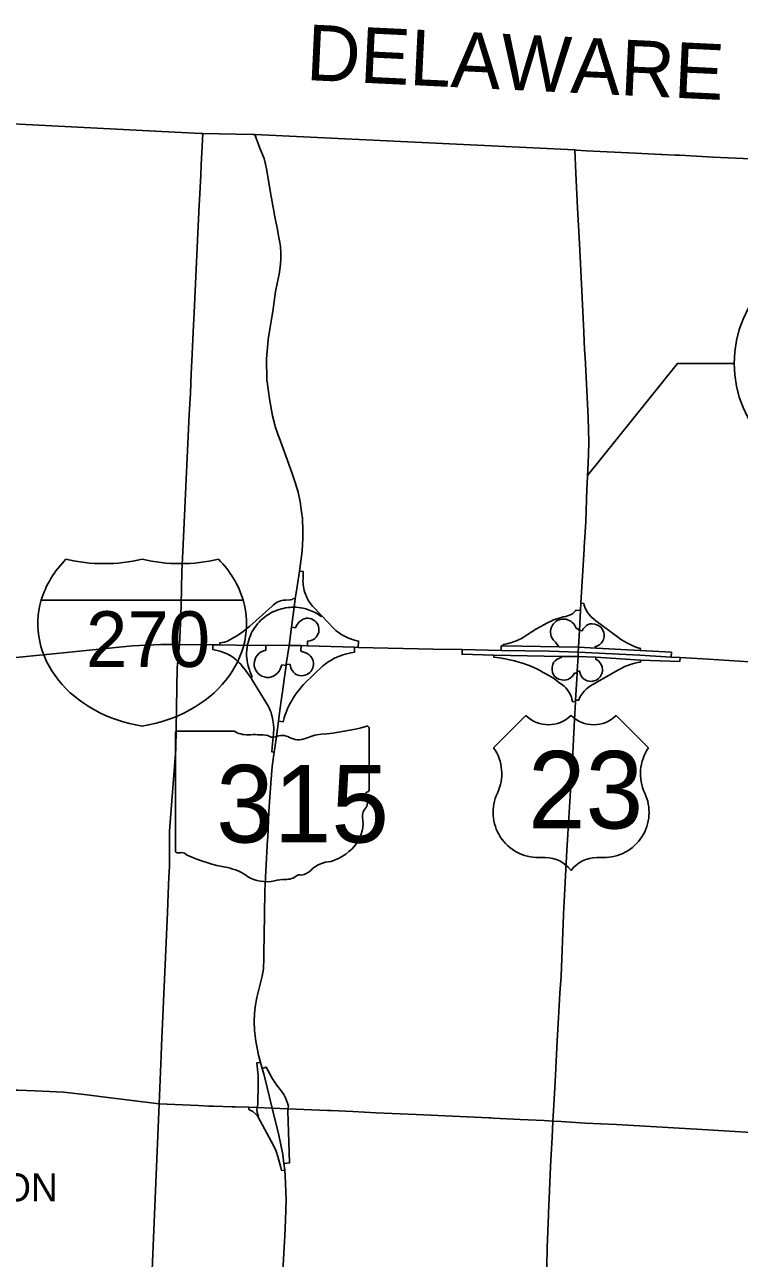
# Model space of a CAD drawing. Extents: x -1146 to -445, y -1283 to -822.
# Drawn here: x -919.9 to -887.8, y -948.5 to -893.1 of the extents above; entities that cross this region are included whole.
import ezdxf

# ---------------------------------------------------------------- set-up
doc = ezdxf.new("R2010")
doc.units = 0
for name, color, linetype in [('Default', 7, 'Continuous'), ('GM_X_Adjacent_County_Text', 7, 'Continuous'), ('GM_X_Corporation_Text', 7, 'Continuous'), ('GM_X_County', 7, 'Continuous'), ('GM_X_Interchange_Ramps', 7, 'Continuous'), ('GM_X_Interstate_Route', 7, 'Continuous'), ('GM_X_Interstate_Shield', 7, 'Continuous'), ('GM_X_State_Route', 7, 'Continuous'), ('GM_X_State_Shield', 7, 'Continuous'), ('GM_X_Township', 7, 'Continuous'), ('GM_X_US_Route', 7, 'Continuous'), ('GM_X_US_Shield', 7, 'Continuous')]:
    doc.layers.add(name, color=color, linetype=linetype)

msp = doc.modelspace()

# ---------------------------------------------------------------- linework, layer by layer
at = {"layer": 'Default'}
msp.add_lwpolyline([(-888.062, -908.344), (-890.609, -908.344), (-894.644, -913.38)], dxfattribs=at)
msp.add_circle((-882.968, -908.344), 5.094, dxfattribs=at)
at = {"layer": 'GM_X_County'}
msp.add_lwpolyline([(-945.796, -896.215), (-936.46, -896.739), (-933.68, -896.859), (-930.577, -897.051), (-929.114, -897.139), (-925.424, -897.327), (-912.021, -898.019), (-911.931, -898.024), (-909.679, -898.071), (-909.589, -898.073), (-895.217, -898.76), (-895.141, -898.773), (-894.703, -898.8), (-892.494, -898.911), (-891.354, -898.969), (-891.291, -898.972), (-890.715, -899.002), (-890.494, -899.002), (-889, -899.078), (-887.326, -899.166)], dxfattribs=at)
at = {"layer": 'GM_X_Interchange_Ramps'}
for points in [[(-904.949, -921.095), (-904.933, -920.816), (-905.121, -920.772), (-905.251, -920.732), (-905.389, -920.68), (-905.507, -920.626), (-905.626, -920.563), (-905.723, -920.504), (-905.808, -920.446), (-905.882, -920.391), (-905.951, -920.335), (-906.014, -920.28), (-906.072, -920.225), (-906.588, -919.681), (-907.001, -919.246), (-907.051, -919.186), (-907.104, -919.113), (-907.14, -919.06), (-907.178, -918.999), (-907.222, -918.921), (-907.258, -918.85), (-907.292, -918.774), (-907.319, -918.705), (-907.345, -918.628), (-907.369, -918.546), (-907.391, -918.456), (-907.408, -918.361), (-907.418, -918.285), (-907.425, -918.203), (-907.428, -918.118), (-907.426, -918.001), (-907.424, -917.698), (-907.424, -917.689), (-907.584, -917.667)], [(-907.777, -918.91), (-907.871, -918.904), (-907.921, -918.944), (-908.002, -918.963), (-908.198, -918.971), (-908.316, -918.98), (-908.439, -919.008), (-908.587, -919.067), (-908.746, -919.187), (-908.811, -919.24), (-909.815, -920.141), (-910.12, -920.384), (-910.377, -920.556), (-910.635, -920.718), (-910.846, -920.831), (-910.959, -920.864), (-911.164, -920.896), (-911.163, -920.988)], [(-906.588, -919.681), (-906.613, -919.705), (-906.668, -919.666), (-906.735, -919.621), (-906.804, -919.579), (-906.885, -919.534), (-906.958, -919.498), (-907.035, -919.463), (-907.107, -919.434), (-907.181, -919.407), (-907.303, -919.369), (-907.414, -919.342), (-907.534, -919.319), (-907.632, -919.306), (-907.732, -919.298), (-907.829, -919.294), (-907.929, -919.295), (-908.017, -919.299), (-908.101, -919.307), (-908.216, -919.324), (-908.32, -919.344), (-908.401, -919.364), (-908.498, -919.392), (-908.593, -919.425), (-908.688, -919.463), (-908.776, -919.503), (-908.869, -919.551), (-908.953, -919.599), (-909.031, -919.648), (-909.101, -919.698), (-909.17, -919.75), (-909.242, -919.81), (-909.316, -919.877), (-909.394, -919.957), (-909.469, -920.041), (-909.534, -920.122), (-909.594, -920.205), (-909.648, -920.287), (-909.705, -920.384), (-909.749, -920.47), (-909.793, -920.565), (-909.833, -920.666), (-909.868, -920.768), (-909.898, -920.874), (-909.918, -920.959), (-909.927, -921.005), (-909.94, -921.082), (-909.956, -921.216), (-909.963, -921.338), (-909.962, -921.477), (-909.956, -921.58), (-909.943, -921.689), (-909.922, -921.811), (-909.895, -921.931), (-909.865, -922.032), (-909.838, -922.111), (-909.818, -922.165), (-909.786, -922.242), (-909.749, -922.321), (-909.708, -922.401), (-909.777, -922.452)], [(-894.966, -919.442), (-895.171, -919.43), (-895.189, -919.454), (-895.253, -919.522), (-895.311, -919.571), (-895.378, -919.616), (-895.455, -919.655), (-895.539, -919.686), (-895.617, -919.705), (-895.733, -919.731), (-895.837, -919.758), (-895.919, -919.781), (-896.032, -919.818), (-896.117, -919.848), (-896.202, -919.881), (-896.282, -919.914), (-896.361, -919.95), (-896.479, -920.007), (-896.905, -920.248), (-896.996, -920.298), (-897.078, -920.347), (-897.155, -920.395), (-897.215, -920.435), (-897.285, -920.484), (-897.351, -920.531), (-897.445, -920.596), (-897.535, -920.65), (-897.614, -920.693), (-897.716, -920.743), (-897.842, -920.799), (-897.936, -920.835), (-898.022, -920.865), (-898.095, -920.888), (-898.165, -920.907), (-898.273, -920.933), (-898.423, -920.963), (-898.424, -921.028)], [(-892.277, -921.239), (-892.271, -921.145), (-892.424, -921.099), (-892.647, -921.017), (-892.885, -920.896), (-893.017, -920.82), (-893.163, -920.727), (-893.303, -920.63), (-894.275, -919.899), (-894.384, -919.812), (-894.5, -919.706), (-894.561, -919.635), (-894.625, -919.547), (-894.676, -919.466), (-894.716, -919.389), (-894.76, -919.29), (-894.79, -919.2), (-894.813, -919.119), (-894.95, -919.11)], [(-907.946, -920.19), (-907.768, -920.215), (-907.722, -920.107), (-907.682, -920.051), (-907.636, -919.999), (-907.582, -919.939), (-907.532, -919.903), (-907.471, -919.859), (-907.425, -919.836), (-907.375, -919.811), (-907.317, -919.801), (-907.269, -919.791), (-907.215, -919.789), (-907.129, -919.797), (-907.045, -919.82), (-906.973, -919.853), (-906.885, -919.916), (-906.833, -919.967), (-906.795, -920.018), (-906.752, -920.098), (-906.727, -920.173), (-906.713, -920.251), (-906.711, -920.324), (-906.722, -920.409), (-906.745, -920.484), (-906.786, -920.566), (-906.839, -920.639), (-906.894, -920.691), (-906.963, -920.74), (-907.036, -920.775), (-907.113, -920.799), (-907.224, -920.812), (-907.233, -921.024)], [(-895.93, -921.069), (-896.091, -920.865), (-896.183, -920.762), (-896.233, -920.688), (-896.272, -920.603), (-896.296, -920.517), (-896.307, -920.434), (-896.305, -920.351), (-896.293, -920.277), (-896.269, -920.196), (-896.225, -920.105), (-896.18, -920.04), (-896.12, -919.977), (-896.05, -919.921), (-895.966, -919.874), (-895.882, -919.844), (-895.772, -919.825), (-895.687, -919.824), (-895.611, -919.834), (-895.543, -919.852), (-895.47, -919.882), (-895.403, -919.921), (-895.337, -919.973), (-895.264, -920.046), (-895.199, -920.139), (-895.151, -920.232), (-895.013, -920.319)], [(-895.013, -920.319), (-894.886, -920.35), (-894.84, -920.268), (-894.778, -920.197), (-894.693, -920.107), (-894.613, -920.066), (-894.53, -920.046), (-894.432, -920.04), (-894.311, -920.051), (-894.222, -920.077), (-894.131, -920.125), (-894.048, -920.193), (-893.997, -920.253), (-893.941, -920.349), (-893.915, -920.424), (-893.899, -920.518), (-893.903, -920.63), (-893.93, -920.736), (-893.977, -920.831), (-894.032, -920.903), (-894.097, -920.964), (-894.167, -921.01), (-894.223, -921.036), (-894.306, -921.06), (-894.263, -921.136)], [(-911.473, -920.982), (-911.478, -921.197), (-911.16, -921.272), (-911.081, -921.294), (-911.006, -921.319), (-910.911, -921.356), (-910.831, -921.392), (-910.756, -921.43), (-910.67, -921.479), (-910.586, -921.532), (-910.518, -921.582), (-910.434, -921.649), (-910.364, -921.711), (-910.291, -921.783), (-910.225, -921.856), (-910.158, -921.939), (-910.1, -922.02), (-910.017, -922.119), (-909.919, -922.257), (-909.777, -922.452), (-909.696, -922.587), (-908.973, -923.757), (-908.93, -923.849), (-908.898, -923.927), (-908.863, -924.025), (-908.836, -924.113), (-908.813, -924.201), (-908.796, -924.279), (-908.779, -924.376), (-908.758, -924.552), (-908.741, -924.731), (-908.749, -924.971), (-908.811, -925.578), (-908.832, -925.784), (-908.721, -925.799)], [(-908.188, -921.908), (-908.374, -921.887), (-908.456, -922.079), (-908.5, -922.161), (-908.576, -922.259), (-908.642, -922.318), (-908.759, -922.39), (-908.844, -922.421), (-908.948, -922.442), (-909.068, -922.443), (-909.178, -922.423), (-909.274, -922.387), (-909.369, -922.331), (-909.463, -922.247), (-909.533, -922.154), (-909.582, -922.054), (-909.614, -921.936), (-909.622, -921.837), (-909.613, -921.73), (-909.583, -921.621), (-909.54, -921.532), (-909.478, -921.443), (-909.406, -921.372), (-909.332, -921.318), (-909.228, -921.267), (-909.099, -921.228), (-909.099, -920.998)], [(-908.531, -924.41), (-908.325, -924.435), (-908.273, -924.257), (-908.239, -924.152), (-908.201, -924.047), (-908.157, -923.937), (-908.104, -923.815), (-908.029, -923.659), (-907.976, -923.557), (-907.904, -923.432), (-907.848, -923.34), (-907.796, -923.26), (-907.734, -923.17), (-907.673, -923.086), (-907.592, -922.982), (-907.499, -922.871), (-907.402, -922.764), (-907.339, -922.697), (-906.537, -921.925), (-906.451, -921.858), (-906.342, -921.78), (-906.236, -921.711), (-906.129, -921.649), (-906.01, -921.586), (-905.914, -921.541), (-905.835, -921.506), (-905.745, -921.471), (-905.645, -921.435), (-905.526, -921.398), (-905.396, -921.364), (-905.279, -921.339), (-905.119, -921.312), (-905.112, -921.086)], [(-907.512, -921.019), (-907.52, -921.26), (-907.341, -921.329), (-907.235, -921.372), (-907.152, -921.426), (-907.086, -921.489), (-907.034, -921.56), (-906.997, -921.63), (-906.971, -921.705), (-906.956, -921.789), (-906.955, -921.868), (-906.964, -921.945), (-906.985, -922.018), (-907.024, -922.102), (-907.068, -922.168), (-907.127, -922.231), (-907.185, -922.276), (-907.25, -922.315), (-907.331, -922.347), (-907.407, -922.363), (-907.487, -922.369), (-907.573, -922.361), (-907.657, -922.34), (-907.73, -922.308), (-907.799, -922.262), (-907.859, -922.202), (-907.904, -922.143), (-907.938, -922.086), (-907.971, -922.01), (-907.993, -921.936), (-908.005, -921.863), (-908.178, -921.843)], [(-890.889, -921.53), (-890.876, -921.312), (-892.277, -921.239), (-894.263, -921.136), (-895.054, -921.086), (-895.93, -921.069), (-898.424, -921.028), (-898.521, -921.027), (-898.523, -921.231)], [(-900.28, -921.197), (-900.279, -921.406), (-898.864, -921.441), (-895.828, -921.499), (-895.073, -921.51), (-894.273, -921.543), (-892.264, -921.664), (-890.503, -921.725), (-890.488, -921.554)], [(-898.864, -921.441), (-898.862, -921.53), (-898.603, -921.563), (-898.353, -921.611), (-898.149, -921.653), (-897.927, -921.706), (-897.728, -921.76), (-897.519, -921.825), (-897.264, -921.915), (-897.064, -921.996), (-896.898, -922.07), (-896.758, -922.143), (-896.632, -922.218), (-896.523, -922.277), (-896.383, -922.357), (-896.276, -922.422), (-896.178, -922.486), (-896.061, -922.574), (-895.928, -922.671), (-895.812, -922.752), (-895.702, -922.845), (-895.618, -922.92), (-895.557, -922.992), (-895.469, -923.124), (-895.415, -923.228), (-895.373, -923.331), (-895.345, -923.421), (-895.322, -923.527), (-895.184, -923.54)], [(-895.117, -922.261), (-895.236, -922.256), (-895.322, -922.393), (-895.419, -922.483), (-895.538, -922.54), (-895.674, -922.569), (-895.807, -922.56), (-895.94, -922.522), (-896.028, -922.473), (-896.11, -922.403), (-896.172, -922.324), (-896.223, -922.218), (-896.242, -922.103), (-896.242, -921.991), (-896.211, -921.867), (-896.168, -921.777), (-896.094, -921.694), (-896.006, -921.626), (-895.907, -921.577), (-895.828, -921.556), (-895.828, -921.499)], [(-895.18, -923.463), (-895.044, -923.47), (-895.002, -923.37), (-894.972, -923.305), (-894.934, -923.242), (-894.887, -923.177), (-894.845, -923.119), (-894.8, -923.063), (-894.744, -923.005), (-894.685, -922.953), (-894.62, -922.903), (-894.556, -922.856), (-894.435, -922.784), (-893.26, -922.105), (-893.137, -922.043), (-893.032, -921.99), (-892.937, -921.946), (-892.84, -921.904), (-892.735, -921.866), (-892.622, -921.832), (-892.519, -921.803), (-892.381, -921.771), (-892.268, -921.756), (-892.264, -921.664)], [(-894.273, -921.543), (-894.273, -921.627), (-894.159, -921.703), (-894.059, -921.819), (-894.019, -921.893), (-893.988, -921.983), (-893.973, -922.071), (-893.975, -922.162), (-893.99, -922.241), (-894.027, -922.335), (-894.084, -922.426), (-894.152, -922.501), (-894.248, -922.562), (-894.356, -922.604), (-894.456, -922.621), (-894.563, -922.616), (-894.668, -922.593), (-894.756, -922.547), (-894.851, -922.478), (-894.918, -922.398), (-894.968, -922.307), (-895.001, -922.169), (-895.113, -922.165)], [(-909.33, -939.732), (-909.497, -939.749), (-909.447, -940.329), (-909.439, -940.71), (-909.463, -941.621), (-909.487, -941.753)], [(-908.102, -941.811), (-908.086, -941.703), (-908.117, -941.562), (-908.219, -941.318), (-908.294, -941.177), (-908.4, -941.028), (-908.62, -940.746), (-908.804, -940.467), (-909.082, -939.941), (-909.255, -940.006)], [(-909.862, -941.742), (-909.862, -941.843), (-909.684, -941.936), (-909.551, -942.054), (-909.477, -942.132), (-909.463, -942.156), (-908.751, -943.458), (-908.632, -943.713), (-908.562, -943.954), (-908.417, -944.447), (-908.392, -944.58), (-908.25, -944.573)], [(-909.487, -941.753), (-909.496, -941.841), (-909.496, -941.843), (-909.481, -941.988), (-909.451, -942.089), (-909.429, -942.132), (-909.463, -942.156)], [(-908.283, -944.273), (-908.04, -944.247), (-908.113, -941.916), (-908.102, -941.811)]]:
    msp.add_lwpolyline(points, dxfattribs=at)
at = {"layer": 'GM_X_Interstate_Route'}
for points in [[(-940.399, -923.41), (-940.223, -923.394), (-939.624, -923.343), (-936.767, -923.076), (-933.009, -922.725), (-929.327, -922.376), (-924.333, -921.901), (-922.171, -921.735), (-918.799, -921.407), (-915.089, -921.031), (-913.815, -920.965), (-913.08, -920.965), (-912.975, -920.974), (-911.473, -920.982), (-911.163, -920.988), (-910.435, -920.998)], [(-910.435, -920.998), (-909.927, -921.005), (-909.099, -920.998), (-908.055, -921.019)], [(-908.055, -921.019), (-908.055, -921.019), (-907.512, -921.019), (-907.233, -921.024), (-905.112, -921.086), (-904.949, -921.095), (-901.586, -921.174), (-900.28, -921.197), (-898.523, -921.231), (-896.354, -921.272), (-895.063, -921.306)], [(-895.063, -921.306), (-892.303, -921.447), (-890.889, -921.53), (-890.488, -921.554)], [(-890.488, -921.554), (-889.219, -921.625), (-885.958, -921.83)]]:
    msp.add_lwpolyline(points, dxfattribs=at)
at = {"layer": 'GM_X_Interstate_Shield'}
msp.add_line((-910.119, -918.969), (-919.184, -918.969), dxfattribs=at)
msp.add_line((-910.119, -918.969), (-919.184, -918.969), dxfattribs=at)
for centre, start_param, end_param in [((-913.479, -920.04), 2.47259, 2.911027), ((-916.363, -912.65), 4.415841, 5.008937), ((-912.939, -912.65), 4.415841, 5.008937), ((-915.823, -920.04), 0.230566, 0.669003), ((-913.479, -920.04), 2.911027, 4.511031), ((-915.823, -920.04), 4.913747, 6.513751)]:
    msp.add_ellipse(centre, major_axis=(5.859, 0), ratio=0.8, start_param=start_param, end_param=end_param, dxfattribs=at)
at = {"layer": 'GM_X_State_Route'}
for points in [[(-908.799, -901.197), (-908.805, -901.167), (-908.857, -900.844), (-909.074, -899.604), (-909.124, -899.346), (-909.176, -899.151), (-909.369, -898.688), (-909.589, -898.073)], [(-908.62, -902.122), (-908.69, -901.766), (-908.753, -901.427), (-908.799, -901.197)], [(-909, -907.293), (-908.998, -907.269), (-908.905, -906.721), (-908.828, -906.268), (-908.785, -906.01), (-908.661, -905.113), (-908.59, -904.752), (-908.501, -904.333), (-908.451, -904.029), (-908.421, -903.693), (-908.421, -903.387), (-908.441, -903.094), (-908.469, -902.916), (-908.514, -902.695), (-908.595, -902.254), (-908.62, -902.122)], [(-908.672, -911.178), (-908.695, -911.11), (-908.796, -910.694), (-908.93, -909.93), (-909.028, -909.273), (-909.052, -909.076), (-909.065, -908.133), (-909, -907.293)], [(-908.503, -911.673), (-908.541, -911.569), (-908.672, -911.178)], [(-908.143, -912.656), (-908.503, -911.673)], [(-907.446, -915.444), (-907.452, -915.31), (-907.491, -915.013), (-907.55, -914.556), (-907.652, -914.123), (-907.775, -913.691), (-907.893, -913.34), (-908.143, -912.656)], [(-907.469, -916.755), (-907.429, -916.191), (-907.432, -915.731), (-907.446, -915.444)], [(-907.691, -918.357), (-907.584, -917.667), (-907.471, -916.781), (-907.469, -916.755)], [(-908.055, -921.019), (-907.946, -920.19), (-907.829, -919.294), (-907.777, -918.91), (-907.691, -918.357)], [(-908.272, -922.534), (-908.188, -921.908), (-908.178, -921.843), (-908.055, -921.019)], [(-908.374, -923.284), (-908.346, -923.089), (-908.272, -922.534)], [(-908.479, -924.035), (-908.374, -923.284)], [(-908.625, -925.105), (-908.576, -924.752), (-908.531, -924.41), (-908.479, -924.035)], [(-908.721, -925.799), (-908.694, -925.6), (-908.625, -925.105)], [(-909.015, -929.718), (-909.01, -929.641), (-908.962, -928.469), (-908.877, -927.2), (-908.808, -926.448), (-908.721, -925.799)], [(-908.81, -941.781), (-909.174, -940.301), (-909.255, -940.006), (-909.33, -939.732), (-909.42, -939.405), (-909.554, -938.773), (-909.611, -938.305), (-909.624, -937.9), (-909.607, -937.549), (-909.584, -937.238), (-909.499, -936.81), (-909.415, -936.453), (-909.264, -935.865), (-909.209, -935.526), (-909.185, -935.048), (-909.18, -934.84), (-909.162, -933.116), (-909.146, -932.029), (-909.1, -931.125), (-909.015, -929.718)], [(-920.317, -940.976), (-920.231, -940.979), (-919.456, -941.009), (-918.184, -941.075), (-917.119, -941.192), (-916.433, -941.283), (-913.888, -941.586), (-912.12, -941.674), (-911.653, -941.693)], [(-911.653, -941.693), (-911.431, -941.702), (-910.604, -941.73), (-910.48, -941.732)], [(-910.48, -941.732), (-909.862, -941.742), (-909.487, -941.753), (-908.81, -941.781)], [(-908.81, -941.781), (-908.102, -941.811), (-906.329, -941.886)], [(-908.283, -944.273), (-908.328, -943.863), (-908.512, -943.006), (-908.81, -941.781)], [(-906.329, -941.886), (-906.162, -941.893), (-905.189, -941.941)], [(-905.189, -941.941), (-904.138, -941.993), (-902.349, -942.064), (-899.078, -942.214), (-898.985, -942.223)], [(-898.985, -942.223), (-898.863, -942.236), (-897.676, -942.296), (-896.587, -942.342), (-896.201, -942.368)], [(-896.201, -942.368), (-895.832, -942.39), (-894.745, -942.457), (-893.343, -942.526), (-891.541, -942.631), (-890.526, -942.687), (-889.734, -942.737), (-888.271, -942.817), (-887.262, -942.874), (-886.455, -942.924), (-885.522, -942.97)], [(-908.22, -946.809), (-908.183, -945.893), (-908.222, -944.825), (-908.25, -944.573), (-908.283, -944.273)], [(-908.513, -952.597), (-908.427, -950.591), (-908.354, -949.36), (-908.249, -947.514), (-908.22, -946.809)]]:
    msp.add_lwpolyline(points, dxfattribs=at)
at = {"layer": 'GM_X_State_Shield'}
for p, q in [((-913.154, -924.947), (-913.154, -930.23)), ((-910.52, -924.856), (-913.069, -924.856)), ((-904.453, -927.488), (-904.453, -924.725)), ((-904.454, -927.488), (-904.453, -927.488))]:
    msp.add_line(p, q, dxfattribs=at)
for centre, major_axis, start_param, end_param in [((-913.054, -924.935), (0.101, 0), 1.712693, 3.28349), ((-909.914, -924.242), (0.978, 0), 4.042523, 4.731795), ((-909.589, -927.822), (3.51, 0), 1.404758, 1.657858), ((-908.793, -924.908), (0.282, 0), 3.836095, 5.185415), ((-908.378, -925.519), (0.586, 0), 0.950623, 2.079405), ((-906.376, -926.469), (1.856, 0), 1.699011, 2.107814), ((-907.553, -917.653), (9.227, 0), 4.814394, 5.042369), ((-904.55, -924.713), (0.0969, 0), 6.141152, 7.989035), ((-907.622, -924.681), (0.705, 0), 4.081561, 5.145723), ((-904.476, -927.691), (0.15, 0), 1.883978, 3.671073), ((-905.429, -928.041), (0.9, 0), 5.934695, 6.695948), ((-904.556, -927.499), (0.104, 0), 5.05454, 6.418171), ((-904.106, -928.645), (0.655, 0), 2.387724, 3.262537), ((-907.036, -928.997), (2.308, 0), 5.101752, 6.440018), ((-913.054, -930.241), (0.102, 0), 3.00124, 4.508301), ((-913.038, -929.701), (0.776, 0), 4.665946, 4.897461), ((-912.879, -930.535), (0.28, 0), 0.519207, 1.627899), ((-909.346, -925.788), (6.663, 0), 4.195997, 4.488961), ((-911.333, -932.603), (2.085, 0), 0.823519, 1.323587), ((-907.664, -930.742), (0.746, 0), 4.937069, 5.64225), ((-906.063, -931.713), (1.264, 0), 1.647645, 2.488434), ((-909.078, -930.561), (1.323, 0), 4.026481, 4.996735), ((-908.314, -932.387), (1.087, 0), 1.495662, 1.94098), ((-908.217, -930.956), (0.705, 0), 4.691044, 5.507374), ((-907.579, -931.468), (0.198, 0), 1.147584, 2.315152)]:
    msp.add_ellipse(centre, major_axis=major_axis, ratio=0.8, start_param=start_param, end_param=end_param, dxfattribs=at)
at = {"layer": 'GM_X_Township'}
msp.add_lwpolyline([(-912.021, -898.019), (-911.931, -898.024), (-911.998, -899.43), (-912.02, -899.893), (-912.073, -900.995), (-912.085, -901.246), (-912.145, -902.5), (-912.316, -906.067), (-912.357, -906.928), (-912.405, -907.931), (-912.447, -908.803), (-912.488, -909.679), (-912.535, -910.637), (-912.83, -916.797), (-912.873, -917.689), (-912.896, -919.205), (-912.931, -920.024), (-912.975, -920.974), (-913.079, -921.996), (-913.134, -925.667), (-913.431, -929.348), (-913.432, -930.941), (-913.452, -931.406), (-913.485, -932.159), (-913.52, -932.996), (-913.606, -935.002), (-913.777, -938.982), (-913.796, -939.433), (-913.888, -941.586), (-914.177, -948.328), (-914.254, -950.134)], dxfattribs=at)
at = {"layer": 'GM_X_US_Route'}
for points in [[(-894.814, -906.944), (-894.906, -905.082), (-895.01, -902.956), (-895.094, -901.371), (-895.172, -899.802), (-895.217, -898.76)], [(-894.757, -908.077), (-894.775, -907.738), (-894.814, -906.944)], [(-894.601, -911.35), (-894.62, -910.766), (-894.757, -908.077)], [(-894.617, -912.752), (-894.605, -912.473), (-894.585, -911.854), (-894.601, -911.35)], [(-894.67, -914.007), (-894.62, -912.825), (-894.617, -912.752)], [(-894.796, -916.678), (-894.791, -916.591), (-894.718, -915.462), (-894.671, -913.96), (-894.68, -914.22), (-894.67, -914.007)], [(-895.063, -921.306), (-895.054, -921.086), (-895.013, -920.319), (-894.966, -919.442), (-894.95, -919.11), (-894.796, -916.678)], [(-895.131, -922.528), (-895.117, -922.261), (-895.113, -922.165), (-895.073, -921.51), (-895.063, -921.306)], [(-895.243, -924.625), (-895.184, -923.54), (-895.18, -923.463), (-895.131, -922.528)], [(-895.373, -927.017), (-895.31, -925.845), (-895.243, -924.625)], [(-895.825, -935.867), (-895.72, -933.101), (-895.719, -933.074), (-895.575, -930.212), (-895.374, -927.037), (-895.373, -927.017)], [(-895.952, -937.723), (-895.924, -937.198), (-895.894, -936.622), (-895.825, -935.867)], [(-896.201, -942.368), (-896.157, -941.652), (-896.104, -940.599), (-896.007, -938.765), (-895.952, -937.723)], [(-896.405, -946.579), (-896.403, -946.508), (-896.359, -945.502), (-896.31, -944.404), (-896.31, -944.394), (-896.24, -943.104), (-896.201, -942.368)], [(-896.897, -955.529), (-896.894, -955.479), (-896.867, -955.024), (-896.842, -954.602), (-896.808, -954.026), (-896.797, -953.835), (-896.795, -953.8), (-896.746, -953.02), (-896.629, -951.135), (-896.621, -951.019), (-896.559, -950.089), (-896.481, -948.913), (-896.452, -948.041), (-896.428, -947.306), (-896.405, -946.579)]]:
    msp.add_lwpolyline(points, dxfattribs=at)
at = {"layer": 'GM_X_US_Shield'}
for p, q in [((-897.415, -924.153), (-898.865, -925.603)), ((-891.904, -925.603), (-893.354, -924.153)), ((-896.835, -930.534), (-896.545, -930.534)), ((-894.225, -930.534), (-893.935, -930.534))]:
    msp.add_line(p, q, dxfattribs=at)
for centre, radius, start, end in [((-896.4, -923.117), 1.45, 225.573, 314.427), ((-894.37, -923.117), 1.45, 225.573, 314.427), ((-900.528, -926.768), 2.03, 334.5471, 35.0009), ((-890.241, -926.768), 2.03, 144.9991, 205.4529), ((-896.858, -928.504), 2.03, 154.8319, 270.6383), ((-893.912, -928.504), 2.03, 269.3617, 25.1681), ((-896.545, -931.984), 1.45, 36.8699, 90), ((-894.225, -931.984), 1.45, 90, 143.1301)]:
    msp.add_arc(centre, radius, start, end, dxfattribs=at)

# ---------------------------------------------------------------- texts
at = {"layer": 'GM_X_Adjacent_County_Text'}
msp.add_text('DELAWARE COUNTY', height=2.5, rotation=357.2562, dxfattribs=at).set_placement((-907.313, -895.62))
at = {"layer": 'GM_X_Corporation_Text'}
msp.add_text('WORTHINGTON', height=1.25, rotation=0, dxfattribs=at).set_placement((-931.254, -945.969))
at = {"layer": 'GM_X_Interstate_Shield'}
msp.add_text('270', height=2.5, dxfattribs=at).set_placement((-917.176, -921.976))
at = {"layer": 'GM_X_State_Shield'}
msp.add_text('315', height=3.4805, dxfattribs=at).set_placement((-911.33, -929.857))
at = {"layer": 'GM_X_US_Shield'}
msp.add_text('23', height=3.4805, dxfattribs=at).set_placement((-897.322, -929.229))

doc.saveas('drawing.dxf')
